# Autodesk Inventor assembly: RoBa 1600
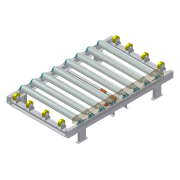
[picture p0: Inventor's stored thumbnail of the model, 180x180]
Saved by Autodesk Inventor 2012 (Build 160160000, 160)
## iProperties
Company: CAD-Verlag
Created: 2004-09
Part Number: RoBa 1600
Document SubType Name: Assembly
Designer: Greiling
Manufacturer: Standard
Standards Organization: Custom
+MSCProtocol1+ProtocolID: P00040924082428305
+MSCProtocol2+Protocol: P00040924082428305<@PID>[Version]<@EL>Version=2.2<@EL>[Main]<@EL>View=MODEL<@EL>DataFile=SpiData|asmpart<@EL>[Acad]<@EL>SmartPart=1<@EL>ReallySmartPart=1<@EL>[O
Control State: 0
Master: False
Checked Out: False
Shininess: 64.0
Length Units: 11269
Angle Units: 11279
Time Units: 11290
Mass Units: 11283
Length Display Precision: 3
Angle Display Precision: 2
Compacted: True
Density: 0.0
Volumn: 0.0
Area: 0.0
PropertySet Name: Model Information
Author: Jürgen Kronas
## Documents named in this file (17)
- C:\DemoDaten2012\CAD Daten\Daten Vault 2012 Inventor\Kapitel 6\6.4\Rollenbahn\Rollenbahn 1400\RoBa.iam
- C:\DemoDaten2012\CAD Daten\Daten Vault 2012 Inventor\Kapitel 6\6.4\Rollenbahn\Rollenbahn 1400\Träger_Antr.iam
- C:\DemoDaten2012\CAD Daten\Daten Vault 2012 Inventor\Kapitel 6\6.4\Rollenbahn\Rollenbahn 1400\schutz_140_3-4.iam
- C:\DemoDaten2012\CAD Daten\Daten Vault 2012 Inventor\Kapitel 6\6.4\Rollenbahn\Rollenbahn 1400\Rolle 1400 kpltiam.iam
- C:\DemoDaten2012\CAD Daten\Daten Vault 2012 Inventor\Kapitel 6\6.4\Rollenbahn\Rollenbahn 1400\Bockrollenträger1400.iam
- C:\DemoDaten2012\CAD Daten\Daten Vault 2012 Inventor\Kapitel 6\6.4\Rollenbahn\Rollenbahn 1400\Motortr_R57.iam
- C:\DemoDaten2012\CAD Daten\Daten Vault 2012 Inventor\Kapitel 6\6.4\Rollenbahn\Rollenbahn 1400\Motorkettenrad_3-4_z17_R57.iam
- C:\DemoDaten2012\CAD Daten\Daten Vault 2012 Inventor\Kapitel 6\6.4\Rollenbahn\Rollenbahn 1400\THRJOIN00AMW0EB.ipt
- C:\DemoDaten2012\CAD Daten\Daten Vault 2012 Inventor\Kapitel 6\6.4\Rollenbahn\Bibliotheken\local.DIN.162.190.8.ipt
- C:\DemoDaten2012\CAD Daten\Daten Vault 2012 Inventor\Kapitel 6\6.4\Rollenbahn\Bibliotheken\local.AFNOR.13.720.8.ipt
- C:\DemoDaten2012\CAD Daten\Daten Vault 2012 Inventor\Kapitel 6\6.4\Rollenbahn\Bibliotheken\I4017A00JQB5MB.ipt
- C:\DemoDaten2012\CAD Daten\Daten Vault 2012 Inventor\Kapitel 6\6.4\Rollenbahn\Bibliotheken\I40320014VA5B.ipt
- C:\DemoDaten2012\CAD Daten\Daten Vault 2012 Inventor\Kapitel 6\6.4\Rollenbahn\Bibliotheken\D125_10016DPSB.ipt
- C:\DemoDaten2012\CAD Daten\Daten Vault 2012 Inventor\Kapitel 6\6.4\Rollenbahn\Rollenbahn 1400\Scheibe.ipt
- C:\DemoDaten2012\CAD Daten\Daten Vault 2012 Inventor\Kapitel 6\6.4\Rollenbahn\Bibliotheken\I4017A001GY0BB.ipt
- C:\DemoDaten2012\CAD Daten\Daten Vault 2012 Inventor\Kapitel 6\6.4\Rollenbahn\Bibliotheken\I4017A0063SJZB.ipt
- C:\DemoDaten2012\CAD Daten\Daten Vault 2012 Inventor\Kapitel 6\6.4\Rollenbahn\Bibliotheken\SEW-Motot.ipt
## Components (43 placed, 16 different names)
1. NF EN 24017  (Regelgewinde) M8 x 16:1 — Einfügen:5
2. DIN 125-1  B B 8.4:1 — Einfügen:5
3. Träger_Antr:1 [sub-assembly] — Fluchtend:1, Fluchtend:2, Passend:1, Passend:3, Passend:48, Passend:113, Passend:115, Passend:128
4. Träger_Antr:2 [sub-assembly] — Fluchtend:1, Fluchtend:2, Passend:1, Passend:96, Passend:97, Passend:117, Passend:119, Passend:129, Passend:130, Passend:131, Passend:132, Passend:133, Passend:134, Passend:135, Passend:136, Winkel:1, Passend:137, Passend:138, Winkel:2
5. Motortr_R57:1 [sub-assembly] — Passend:119, Passend:123, Passend:127
6. schutz_140_3-4:1 [sub-assembly] — Passend:3
7. SEW-Motot:1
8. Bockrollenträger1400:2 [sub-assembly]
9. Bockrollenträger1400:1 [sub-assembly]
10. Motorkettenrad_3-4_z17_R57:1 [sub-assembly] — Fluchtend:3
11. Verschraubung 8 - 40:1
12. Scheibe:1 — Einfügen:11
13. Sechskantschraube DIN 933 - M12x25:1 — Einfügen:11
14. Sechskantschraube DIN EN ISO 4017 - M10x80_1:1 — Passend:48
15. NF EN 24017  (Regelgewinde) M8 x 16:3 — Einfügen:14
16. DIN 125-1  B B 8.4:3 — Einfügen:14
17. NF EN 24017  (Regelgewinde) M8 x 16:4 — Einfügen:32
18. DIN 125-1  B B 8.4:4 — Einfügen:32
19. Sechskantschraube DIN EN ISO 4017 - M10x80_1:2 — Passend:97
20. Sechskantschraube DIN EN ISO 4017 - M10x80_1:3 — Passend:96
21. Rolle 1400 kpltiam:1 [sub-assembly] — Passend:116, Passend:117, Fluchtend:3, Fluchtend:4, Passend:129
22. Sechskantschraube DIN EN ISO 4017 - M10x80_1:4 — Passend:115, Passend:116
23. NF EN 24017  (Regelgewinde) M8 x 16:5 — Einfügen:41
24. DIN 125-1  B B 8.4:5 — Einfügen:41
25. Rolle 1400 kpltiam:2 [sub-assembly] — Fluchtend:4, Fluchtend:5, Fluchtend:8, Fluchtend:9, Fluchtend:10, Fluchtend:11, Passend:128, Passend:130
26. Rolle 1400 kpltiam:3 [sub-assembly] — Fluchtend:5, Fluchtend:6, Fluchtend:9, Passend:131
27. Rolle 1400 kpltiam:4 [sub-assembly] — Fluchtend:6, Fluchtend:7, Fluchtend:10, Fluchtend:12, Passend:133
28. Rolle 1400 kpltiam:5 [sub-assembly] — Fluchtend:8, Fluchtend:12, Passend:134
29. Rolle 1400 kpltiam:6 [sub-assembly] — Fluchtend:7, Fluchtend:11, Passend:132
30. Rolle 1400 kpltiam:7 [sub-assembly] — Passend:135, Passend:136, Winkel:1
31. Rolle 1400 kpltiam:8 [sub-assembly] — Passend:137, Passend:138, Winkel:2
32. Mutter DIN EN 24 032 M12_1:1 — Einfügen:10
33. Sechskantschraube DIN 933 - M12x50:1 — Passend:45
34. Unterlegscheibe DIN 125-B 12:1 — Passend:45, Einfügen:10, Passend:123
35. Unterlegscheibe DIN 125-B 12:4 — Passend:124, Passend:126, Passend:127
36. Mutter DIN EN 24 032 M12_1:4 — Passend:125, Passend:126
37. Sechskantschraube DIN 933 - M12x50:4 — Passend:124, Passend:125
38. Mutter DIN EN 24 032 M12_1:5
39. Sechskantschraube DIN 933 - M12x50:5
40. Unterlegscheibe DIN 125-B 12:5
41. Unterlegscheibe DIN 125-B 12:6
42. Mutter DIN EN 24 032 M12_1:6
43. Sechskantschraube DIN 933 - M12x50:6
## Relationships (47: Mate 27, Flush 12, Insert 6, Angle 2)
- Fluchtend:1 [Flush]: Träger_Antr:1 ↔ Träger_Antr:2
- Fluchtend:2 [Flush]: Träger_Antr:1 ↔ Träger_Antr:2
- Passend:1 [Mate]: Träger_Antr:1 ↔ Träger_Antr:2
- Passend:3 [Mate]: Träger_Antr:1 ↔ schutz_140_3-4:1
- Einfügen:5 [Insert]: NF EN 24017  (Regelgewinde) M8 x 16:1 ↔ DIN 125-1  B B 8.4:1
- Passend:45 [Mate]: Sechskantschraube DIN 933 - M12x50:1 ↔ Unterlegscheibe DIN 125-B 12:1
- Einfügen:10 [Insert]: Mutter DIN EN 24 032 M12_1:1 ↔ Unterlegscheibe DIN 125-B 12:1
- Einfügen:11 [Insert]: Scheibe:1 ↔ Sechskantschraube DIN 933 - M12x25:1
- Passend:48 [Mate]: Träger_Antr:1 ↔ Sechskantschraube DIN EN ISO 4017 - M10x80_1:1
- Einfügen:14 [Insert]: NF EN 24017  (Regelgewinde) M8 x 16:3 ↔ DIN 125-1  B B 8.4:3
- Passend:96 [Mate]: Träger_Antr:2 ↔ Sechskantschraube DIN EN ISO 4017 - M10x80_1:3
- Passend:97 [Mate]: Träger_Antr:2 ↔ Sechskantschraube DIN EN ISO 4017 - M10x80_1:2
- Einfügen:32 [Insert]: NF EN 24017  (Regelgewinde) M8 x 16:4 ↔ DIN 125-1  B B 8.4:4
- Passend:113 [Mate]: Träger_Antr:1
- Passend:115 [Mate]: Träger_Antr:1 ↔ Sechskantschraube DIN EN ISO 4017 - M10x80_1:4
- Passend:116 [Mate]: Rolle 1400 kpltiam:1 ↔ Sechskantschraube DIN EN ISO 4017 - M10x80_1:4
- Passend:117 [Mate]: Träger_Antr:2 ↔ Rolle 1400 kpltiam:1
- Fluchtend:3 [Flush]: Motorkettenrad_3-4_z17_R57:1 ↔ Rolle 1400 kpltiam:1
- Passend:119 [Mate]: Träger_Antr:2 ↔ Motortr_R57:1
- Passend:123 [Mate]: Motortr_R57:1 ↔ Unterlegscheibe DIN 125-B 12:1
- Passend:124 [Mate]: Unterlegscheibe DIN 125-B 12:4 ↔ Sechskantschraube DIN 933 - M12x50:4
- Passend:125 [Mate]: Mutter DIN EN 24 032 M12_1:4 ↔ Sechskantschraube DIN 933 - M12x50:4
- Passend:126 [Mate]: Unterlegscheibe DIN 125-B 12:4 ↔ Mutter DIN EN 24 032 M12_1:4
- Passend:127 [Mate]: Motortr_R57:1 ↔ Unterlegscheibe DIN 125-B 12:4
- Einfügen:41 [Insert]: NF EN 24017  (Regelgewinde) M8 x 16:5 ↔ DIN 125-1  B B 8.4:5
- Fluchtend:4 [Flush]: Rolle 1400 kpltiam:1 ↔ Rolle 1400 kpltiam:2
- Fluchtend:5 [Flush]: Rolle 1400 kpltiam:2 ↔ Rolle 1400 kpltiam:3
- Fluchtend:6 [Flush]: Rolle 1400 kpltiam:3 ↔ Rolle 1400 kpltiam:4
- Fluchtend:7 [Flush]: Rolle 1400 kpltiam:4 ↔ Rolle 1400 kpltiam:6
- Fluchtend:8 [Flush]: Rolle 1400 kpltiam:2 ↔ Rolle 1400 kpltiam:5
- Fluchtend:9 [Flush]: Rolle 1400 kpltiam:2 ↔ Rolle 1400 kpltiam:3
- Fluchtend:10 [Flush]: Rolle 1400 kpltiam:2 ↔ Rolle 1400 kpltiam:4
- Fluchtend:11 [Flush]: Rolle 1400 kpltiam:2 ↔ Rolle 1400 kpltiam:6
- Fluchtend:12 [Flush]: Rolle 1400 kpltiam:4 ↔ Rolle 1400 kpltiam:5
- Passend:128 [Mate]: Träger_Antr:1 ↔ Rolle 1400 kpltiam:2
- Passend:129 [Mate]: Träger_Antr:2 ↔ Rolle 1400 kpltiam:1
- Passend:130 [Mate]: Träger_Antr:2 ↔ Rolle 1400 kpltiam:2
- Passend:131 [Mate]: Träger_Antr:2 ↔ Rolle 1400 kpltiam:3
- Passend:132 [Mate]: Träger_Antr:2 ↔ Rolle 1400 kpltiam:6
- Passend:133 [Mate]: Träger_Antr:2 ↔ Rolle 1400 kpltiam:4
- Passend:134 [Mate]: Träger_Antr:2 ↔ Rolle 1400 kpltiam:5
- Passend:135 [Mate]: Träger_Antr:2 ↔ Rolle 1400 kpltiam:7
- Passend:136 [Mate]: Träger_Antr:2 ↔ Rolle 1400 kpltiam:7
- Winkel:1 [Angle]: Träger_Antr:2 ↔ Rolle 1400 kpltiam:7
- Passend:137 [Mate]: Träger_Antr:2 ↔ Rolle 1400 kpltiam:8
- Passend:138 [Mate]: Träger_Antr:2 ↔ Rolle 1400 kpltiam:8
- Winkel:2 [Angle]: Träger_Antr:2 ↔ Rolle 1400 kpltiam:8
